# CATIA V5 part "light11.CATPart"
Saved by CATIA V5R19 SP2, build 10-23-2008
Part number: light11
Bounding box of the stored display mesh (mm): x 1468.435 to 1831.329, y -626.02 to 626.021, z 338.281 to 543.852
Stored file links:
  C:\BEHROOZ\catia learning\tarh haye mashin\hb\light11.CATPart
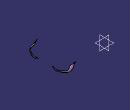
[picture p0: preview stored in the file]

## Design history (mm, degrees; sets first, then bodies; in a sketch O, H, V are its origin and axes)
Body1 (main body)
  Set1
    DatumSurface1
    ThickSurface1: Surface DatumSurface1, TopOffset 1, BotOffset 0
    DatumSurface2
    ThickSurface2: Surface DatumSurface2, TopOffset 1, BotOffset 0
